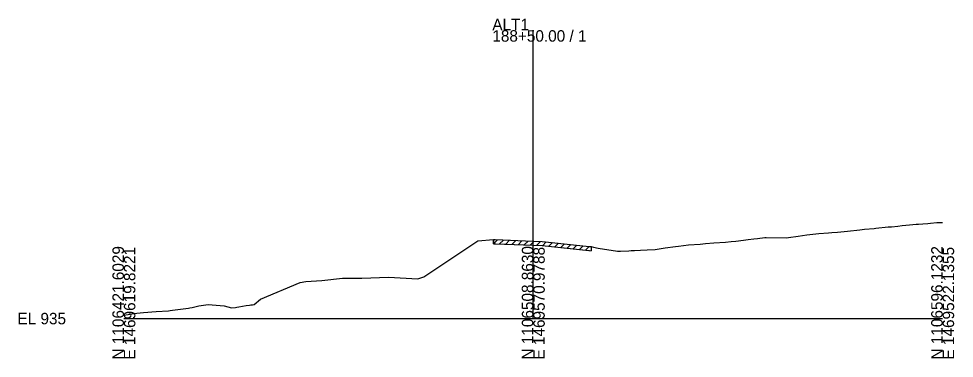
# Model space of a CAD drawing. Extents: x -26 to 2203, y -10 to 19568.
# Drawn here: x 1974.3 to 2202.8, y 10490.3 to 10573.2 of the extents above; entities that cross this region are included whole.
import ezdxf

# ---------------------------------------------------------------- set-up
doc = ezdxf.new("R2010")
doc.units = 0
for name, color, linetype in [('RD_GPK_XS_Cell', 7, 'Continuous'), ('RD_XS_ExGround', 7, 'Continuous'), ('RD_XS_ExPaveRet', 7, 'Continuous')]:
    doc.layers.add(name, color=color, linetype=linetype)

msp = doc.modelspace()

# ---------------------------------------------------------------- linework, layer by layer
at = {"layer": 'RD_GPK_XS_Cell'}
for p, q in [((2100, 10500), (2100, 10570.38)), ((2000, 10500), (2100, 10500)), ((2100, 10500), (2200, 10500))]:
    msp.add_line(p, q, dxfattribs=at)
at = {"layer": 'RD_XS_ExGround'}
msp.add_lwpolyline([(2000, 10500.86), (2001.03, 10501), (2002.37, 10501.2), (2004.75, 10501.46), (2007.9, 10501.72), (2010.9, 10501.91), (2011.34, 10501.97), (2011.91, 10502.04), (2015.78, 10502.55), (2016.08, 10502.61), (2016.66, 10502.72), (2018.32, 10503.07), (2020.59, 10503.46), (2024.47, 10503.14), (2026.32, 10502.65), (2027.23, 10502.73), (2027.55, 10502.82), (2028.07, 10502.88), (2029.89, 10503.17), (2030.65, 10503.27), (2031.04, 10503.31), (2031.43, 10503.36), (2031.81, 10503.44), (2033.35, 10504.74), (2043.07, 10508.83), (2044.44, 10509.05), (2048.34, 10509.32), (2053.42, 10509.82), (2055.46, 10509.87), (2058.16, 10509.83), (2064.62, 10510.13), (2071.84, 10509.71), (2073.25, 10510.21), (2086.44, 10518.97), (2090.27, 10519.28), (2090.69, 10519.26), (2100, 10518.89), (2102.16, 10518.8), (2113.69, 10517.6), (2114.17, 10517.55), (2114.67, 10517.45), (2115.87, 10517.19), (2120.55, 10516.46), (2121.3, 10516.44), (2123.38, 10516.53), (2123.95, 10516.6), (2124.42, 10516.63), (2124.75, 10516.63), (2126.16, 10516.66), (2127.86, 10516.78), (2129.8, 10516.87), (2132.2, 10517.3), (2134.73, 10517.58), (2135.44, 10517.66), (2137.92, 10518.02), (2140.8, 10518.19), (2142.08, 10518.28), (2144.07, 10518.51), (2146.97, 10518.67), (2148.36, 10518.78), (2149.44, 10518.89), (2151.32, 10519.1), (2152.51, 10519.29), (2153.89, 10519.42), (2154.78, 10519.51), (2156.54, 10519.77), (2156.87, 10519.79), (2161.77, 10519.74), (2162.34, 10519.75), (2164.69, 10520.11), (2166.82, 10520.47), (2169.75, 10520.75), (2172.09, 10520.95), (2172.93, 10521), (2174.29, 10521.09), (2176.73, 10521.32), (2179.8, 10521.68), (2180.91, 10521.83), (2183.24, 10522), (2183.71, 10522.04), (2186.68, 10522.37), (2187.52, 10522.41), (2189.02, 10522.59), (2190.12, 10522.71), (2191.93, 10522.86), (2193.56, 10523), (2194.13, 10523.05), (2195.16, 10523.13), (2196.34, 10523.23), (2196.99, 10523.29), (2198.54, 10523.41), (2200, 10523.46)], dxfattribs=at)
at = {"layer": 'RD_XS_ExPaveRet'}
for p, q in [((2090.27, 10519.28), (2090.27, 10518.28)), ((2090.27, 10518.27), (2090.27, 10519.27)), ((2090.27, 10518.27), (2091.23, 10519.23)), ((2090.27, 10518.3), (2090.84, 10518.27)), ((2090.27, 10518.3), (2090.27, 10518.3)), ((2090.27, 10518.27), (2090.62, 10518.26)), ((2090.62, 10518.26), (2100, 10517.88)), ((2090.69, 10518.26), (2100, 10517.89)), ((2090.84, 10518.27), (2100, 10517.91)), ((2091.77, 10518.21), (2092.73, 10519.17)), ((2093.27, 10518.15), (2094.23, 10519.11)), ((2094.77, 10518.09), (2095.73, 10519.05)), ((2096.27, 10518.03), (2097.23, 10518.99)), ((2097.77, 10517.97), (2098.73, 10518.93)), ((2099.27, 10517.91), (2100.23, 10518.87)), ((2100, 10517.88), (2102.16, 10517.8)), ((2100.77, 10517.85), (2101.73, 10518.81)), ((2102.16, 10517.8), (2113.69, 10516.6)), ((2102.17, 10517.82), (2113.54, 10516.63)), ((2102.27, 10517.79), (2103.16, 10518.69)), ((2103.77, 10517.64), (2104.66, 10518.54)), ((2105.27, 10517.48), (2106.16, 10518.38)), ((2106.77, 10517.32), (2107.66, 10518.22)), ((2108.27, 10517.17), (2109.16, 10518.06)), ((2109.77, 10517.01), (2110.66, 10517.91)), ((2111.27, 10516.85), (2112.16, 10517.75)), ((2112.77, 10516.69), (2113.67, 10517.59)), ((2114.17, 10517.56), (2114.17, 10516.56)), ((2114.17, 10517.55), (2114.17, 10516.55)), ((2113.54, 10516.63), (2114.17, 10516.56)), ((2113.75, 10516.58), (2114.17, 10516.54)), ((2114.17, 10516.54), (2114.17, 10516.54))]:
    msp.add_line(p, q, dxfattribs=at)

# ---------------------------------------------------------------- texts
at = {"layer": 'RD_GPK_XS_Cell'}
for s, p in [('ALT1', (2090, 10570.38)), ('188+50.00 / 1', (2090, 10567.58)), ('EL 935', (1974, 10498.6))]:
    msp.add_text(s, height=2.8, dxfattribs=at).set_placement(p)
for s, p in [('N 1106421.6029', (2000, 10490)), ('E 1469619.8221', (2002.8, 10490)), ('N 1106508.8630', (2100, 10490)), ('E 1469570.9788', (2102.8, 10490)), ('N 1106596.1232', (2200, 10490)), ('E 1469522.1355', (2202.8, 10490))]:
    msp.add_text(s, height=2.8, rotation=90, dxfattribs=at).set_placement(p)

doc.saveas('drawing.dxf')
